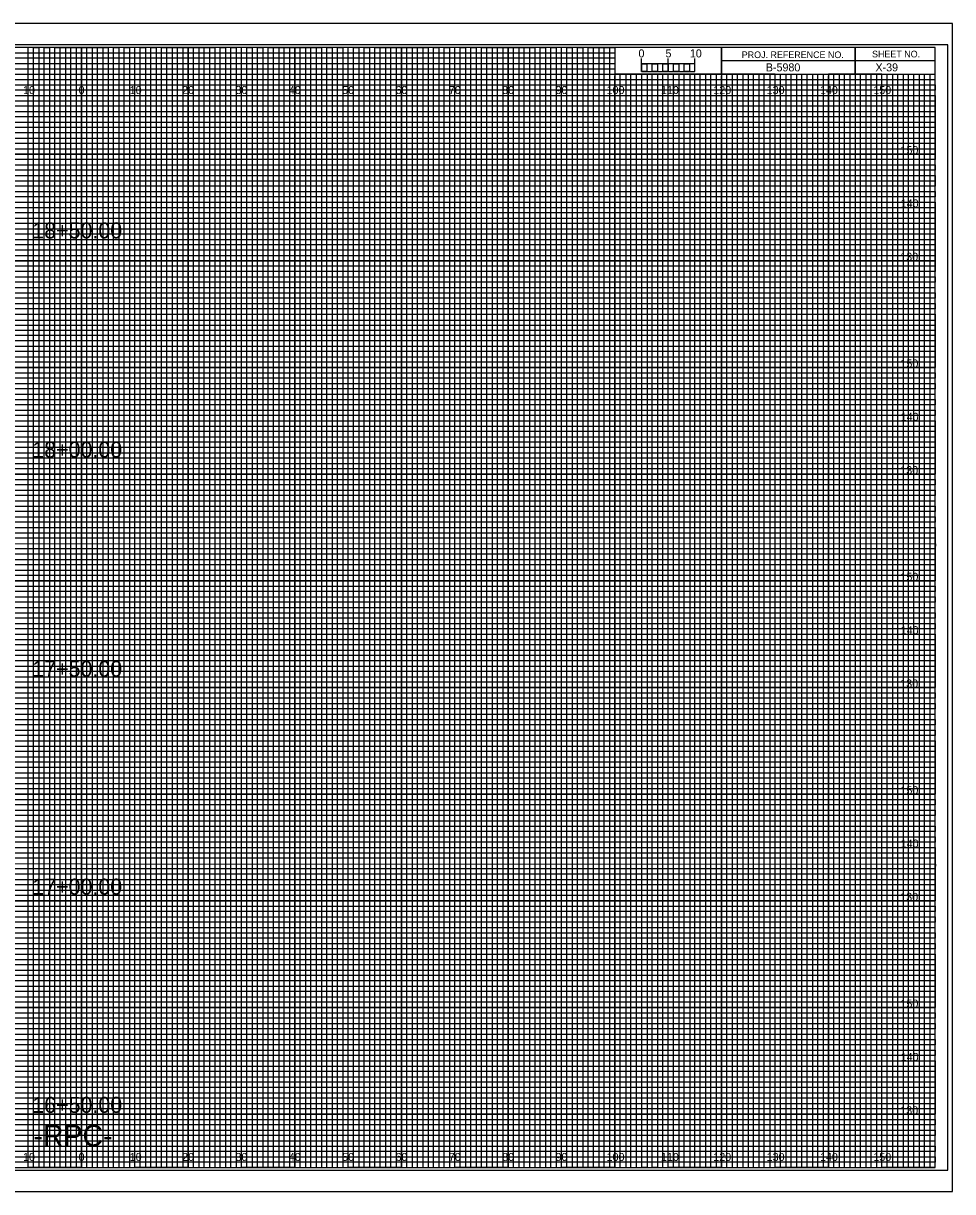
# Model space of a CAD drawing. Extents: x -13 to 323, y -5 to 874.
# Drawn here: x 149.1 to 323.3, y 215.5 to 434.5 of the extents above; entities that cross this region are included whole.
import ezdxf

# ---------------------------------------------------------------- set-up
doc = ezdxf.new("R2010")
doc.units = 0
for name, color, linetype in [('Exist Cross Section Cell', 7, 'Continuous'), ('Exist XS Center Line Elevation Label', 7, 'Continuous'), ('Exist XS Ground Line', 7, 'Continuous'), ('Prop CMT Conc Surface', 7, 'Continuous'), ('Prop CMT Concrete Structures', 7, 'Continuous'), ('Prop CMT Pvmt Course 1', 7, 'Continuous'), ('Prop CMT Pvmt Course 1 CG', 7, 'Continuous'), ('Prop CMT Pvmt Course 2', 7, 'Continuous'), ('Prop CMT Pvmt Course 3', 7, 'Continuous'), ('Prop CMT Pvmt Surface', 7, 'Continuous'), ('Prop CMT Pvmt Surface Shoulder', 7, 'Continuous'), ('Prop CMT Shld Paved Course 1', 7, 'Continuous'), ('Prop CMT Shld Paved Course 2', 7, 'Continuous'), ('Prop CMT Shld Paved Course 3', 7, 'Continuous'), ('Prop CMT Slope Grass', 7, 'Continuous'), ('Prop CMT Subgrade Earthwork', 7, 'Continuous'), ('Scratch_Level_1', 7, 'Continuous')]:
    doc.layers.add(name, color=color, linetype=linetype)

msp = doc.modelspace()

# ---------------------------------------------------------------- linework, layer by layer
at = {"layer": 'Exist XS Center Line Elevation Label'}
for points in [[(145, 220), (155, 220), (155, 430), (165, 430), (165, 220), (175, 220), (175, 430), (185, 430), (185, 220), (195, 220), (195, 430), (205, 430), (205, 220), (215, 220), (215, 430), (225, 430), (225, 220), (235, 220), (235, 430), (245, 430), (245, 220), (255, 220), (255, 430), (259.93, 430), (260, 430), (260, 425), (264.99, 425), (264.99, 220), (275, 220), (275, 425), (285, 425), (285, 220), (295, 220), (295, 425), (305, 425), (305, 220), (315, 220), (315, 425)], [(0, 425), (275, 425)], [(0, 405), (320, 405), (320, 415), (0, 415)], [(0, 385), (320, 385), (320, 395), (0, 395)], [(0, 365), (320, 365), (320, 375), (0, 375)], [(0, 345), (320, 345), (320, 355), (0, 355)], [(0, 325), (320, 325), (320, 335), (0, 335)], [(0, 305), (320, 305), (320, 315), (0, 315)], [(0, 285), (320, 285), (320, 295), (0, 295)], [(0, 265), (320, 265), (320, 275), (0, 275)], [(0, 245), (320, 245), (320, 255), (0, 255)], [(0, 225), (320, 225), (320, 235), (0, 235)]]:
    msp.add_lwpolyline(points, dxfattribs=at)
at = {"layer": 'Exist XS Ground Line'}
for p, q in [((150, 430), (140, 430)), ((150, 220), (150, 430)), ((170, 430), (160, 430)), ((160, 430), (160, 220)), ((170, 220), (170, 430)), ((190, 430), (180, 430)), ((180, 430), (180, 220)), ((190, 220), (190, 430)), ((210, 430), (200, 430)), ((200, 430), (200, 220)), ((210, 220), (210, 430)), ((230, 430), (220, 430)), ((220, 430), (220, 220)), ((230, 220), (230, 430)), ((250, 430), (240, 430)), ((240, 430), (240, 220)), ((250, 220), (250, 430)), ((260, 430), (260, 220)), ((270, 220), (270, 425)), ((290, 425), (280, 425)), ((280, 425), (280, 220)), ((290, 220), (290, 425)), ((310, 425), (300, 425)), ((300, 425), (300, 220)), ((310, 220), (310, 425)), ((160, 220), (150, 220)), ((180, 220), (170, 220)), ((200, 220), (190, 220)), ((220, 220), (210, 220)), ((240, 220), (230, 220)), ((260, 220), (250, 220)), ((280, 220), (270, 220)), ((300, 220), (290, 220)), ((320, 220), (310, 220)), ((320, 220), (320, 220))]:
    msp.add_line(p, q, dxfattribs=at)
for points in [[(0, 420), (320, 420), (320, 410), (0, 410)], [(0, 400), (320, 400), (320, 390), (0, 390)], [(0, 380), (320, 380), (320, 370), (0, 370)], [(0, 360), (320, 360), (320, 350), (0, 350)], [(0, 340), (320, 340), (320, 330), (0, 330)], [(0, 320), (320, 320), (320, 310), (0, 310)], [(0, 300), (320, 300), (320, 290), (0, 290)], [(0, 280), (320, 280), (320, 270), (0, 270)], [(0, 260), (320, 260), (320, 250), (0, 250)], [(0, 240), (320, 240), (320, 230), (0, 230)]]:
    msp.add_lwpolyline(points, dxfattribs=at)
at = {"layer": 'Prop CMT Pvmt Course 2'}
for p, q in [((265, 425.49), (265, 427.9)), ((265, 426.9), (265, 427.9)), ((270, 425.49), (270, 427.9)), ((275, 425.49), (275, 427.9)), ((275, 426.9), (275, 427.9))]:
    msp.add_line(p, q, dxfattribs=at)
for points in [[(275, 426.9), (265, 426.9), (265, 425.49), (275, 425.49)], [(265, 426.9), (266, 426.9), (266, 425.49), (265, 425.49)], [(267, 426.9), (268, 426.9), (268, 425.49), (267, 425.49)], [(269, 426.9), (270, 426.9), (270, 425.49), (269, 425.49)], [(271, 426.9), (272, 426.9), (272, 425.49), (271, 425.49)], [(273, 426.9), (274, 426.9), (274, 425.49), (273, 425.49)]]:
    msp.add_lwpolyline(points, close=True, dxfattribs=at)
at = {"layer": 'Prop CMT Pvmt Course 3'}
msp.add_lwpolyline([(-13.4, 215.5), (323.3, 215.5), (323.3, 434.5), (-13.4, 434.5)], close=True, dxfattribs=at)
at = {"layer": 'Prop CMT Pvmt Surface'}
for p, q in [((150, 220), (150, 430)), ((160, 220), (160, 430)), ((170, 220), (170, 430)), ((180, 220), (180, 430)), ((190, 220), (190, 430)), ((200, 220), (200, 430)), ((210, 220), (210, 430)), ((220, 220), (220, 430)), ((230, 220), (230, 430)), ((240, 220), (240, 430)), ((250, 220), (250, 430)), ((260, 220), (260, 424.69)), ((270, 220), (270, 424.69)), ((280, 220), (280, 424.69)), ((290, 220), (290, 424.69)), ((300, 220), (300, 424.69)), ((310, 220), (310, 424.69)), ((0, 420), (320, 420)), ((0, 410), (320, 410)), ((0, 400), (320, 400)), ((0, 390), (320, 390)), ((0, 380), (320, 380)), ((0, 370), (320, 370)), ((0, 360), (320, 360)), ((0, 350), (320, 350)), ((0, 340), (320, 340)), ((0, 330), (320, 330)), ((0, 320), (320, 320)), ((0, 310), (320, 310)), ((0, 300), (320, 300)), ((0, 290), (320, 290)), ((0, 280), (320, 280)), ((0, 270), (320, 270)), ((0, 260), (320, 260)), ((0, 250), (320, 250)), ((0, 240), (320, 240)), ((0, 230), (320, 230))]:
    msp.add_line(p, q, dxfattribs=at)
at = {"layer": 'Prop CMT Pvmt Surface Shoulder'}
for p, q in [((323.3, 434.5), (-13.4, 434.5)), ((-13.4, 215.5), (323.3, 215.5))]:
    msp.add_line(p, q, dxfattribs=at)
at = {"layer": 'Prop CMT Shld Paved Course 1'}
for p, q in [((0, 429), (260, 429)), ((260, 427.98), (0, 427.98)), ((260, 429), (260, 427.98)), ((0, 427), (260, 427)), ((260, 425.89), (0, 425.89)), ((260, 427), (260, 425.89)), ((0, 424), (320, 424))]:
    msp.add_line(p, q, dxfattribs=at)
for points in [[(0, 423), (270, 423), (320, 423), (320, 422), (0, 422)], [(0, 421), (320, 421), (320, 419), (0, 419)], [(0, 418), (320, 418), (320, 417), (0, 416.98)], [(0, 416), (320, 416), (320, 414), (0, 414)], [(0, 413), (320, 413), (320, 412), (0, 412)], [(0, 411), (320, 411), (320, 409), (0, 409)], [(0, 408), (320, 408), (320, 407), (0, 407)], [(0, 406), (320, 406), (320, 404), (0, 404)], [(0, 403), (320, 403), (320, 402), (0, 402)], [(0, 401), (320, 401), (320, 399), (0, 399)], [(0, 398), (320, 398), (320, 397), (0, 397)], [(0, 396), (320, 396), (320, 393.95), (320, 393), (320, 392), (0, 392)], [(0, 394), (320, 394), (320, 393), (0, 393)], [(0, 391), (320, 391), (320, 389), (0, 389.03)], [(0, 389.03), (320, 389), (320, 388), (0, 388)], [(0, 387), (320, 387), (320, 386), (0, 386)], [(0, 384), (320, 384), (320, 383), (0, 383)], [(0, 382), (320, 382), (320, 381), (0, 381)], [(-0.07, 378.89), (320, 378.89), (320, 377.88), (-0.07, 377.88)], [(0, 377), (320, 377), (320, 376), (0, 376)], [(0, 374), (320, 374), (320, 373), (0, 373)], [(0, 372), (320, 372), (320, 371), (0, 371)], [(0, 369), (320, 369), (320, 368), (0, 368)], [(0, 367), (320, 367), (320, 366), (0, 366)], [(0, 364), (320, 364), (320, 363), (0, 363)], [(0, 362), (320, 362), (320, 361), (0, 361)], [(0, 359), (320, 359), (319.99, 357.98), (0, 358)], [(0, 357), (320, 357), (320, 356), (0, 356)], [(0, 354), (320, 354), (320, 353), (0, 353)], [(0, 352), (320, 352), (320, 351), (0, 351)], [(0, 349), (320, 349), (320, 348), (0, 348)], [(0, 347), (320, 347), (320, 346), (0, 346)], [(0, 344), (320, 344), (320, 343), (0, 343)], [(0, 342), (320, 342), (320, 341), (0, 341)], [(0, 339), (320, 339), (320, 338), (0, 338)], [(0, 336.99), (320.07, 336.91), (320, 336), (0, 336)], [(0, 334), (320, 334), (320, 333), (0, 333)], [(0, 332), (320, 332), (320, 331), (0, 331)], [(0, 329), (320, 329), (320, 328), (0, 328)], [(0, 327), (320, 327), (320, 326), (0, 326)], [(0, 324), (320, 324), (320, 323), (0, 323)], [(0, 322), (320, 322), (320, 321), (0, 321)], [(0, 319), (320, 319), (320, 318), (0, 318)], [(0, 317), (320, 317), (320, 316), (0, 316)], [(0, 314), (320, 314), (320, 313), (0, 313)], [(0, 312), (320, 312), (320, 311), (0, 311)], [(0, 309), (320, 309), (320, 308), (0, 308)], [(0, 307), (320, 307), (320, 306), (0, 306)], [(0, 304), (320, 304), (320, 303), (0, 303)], [(0, 302), (320, 302), (320, 301), (0, 301)], [(0, 299), (320, 299), (319.99, 297.98), (0, 298)], [(0, 297), (320, 297), (320, 296), (0, 296)], [(0, 294), (320, 294), (320, 293), (0, 293)], [(0, 292), (320, 292), (320, 291), (0, 291)], [(0, 289), (320, 289), (320, 288), (0, 288)], [(0, 287), (320, 287), (320, 286), (0, 286)], [(0, 284), (320, 284), (320, 283), (0, 283)], [(0, 282), (320, 282), (320, 281), (0, 281)], [(0, 279), (320, 279), (320, 278), (0, 278)], [(0, 276.99), (320.07, 276.91), (320, 276), (0, 276)], [(0, 274), (320, 274), (320, 273), (0, 273)], [(0, 272), (320, 272), (320, 271), (0, 271)], [(0, 269), (320, 269), (320, 268), (0, 268)], [(0, 267), (320, 267), (320, 266), (0, 266)], [(0, 264), (320, 264), (320, 263), (0, 263)], [(0, 262), (320, 262), (320, 261), (0, 261)], [(0, 259), (320, 259), (320, 258), (0, 258)], [(0, 257), (320, 257), (320, 256), (0, 256)], [(0, 254), (320, 254), (320, 253), (0, 253)], [(0, 252), (320, 252), (320, 251), (0, 251)], [(0, 249), (320, 249), (320, 248), (0, 248)], [(0, 247), (320, 247), (320, 246), (0, 246)], [(0, 244), (320, 244), (320, 243), (0, 243)], [(0, 242), (320, 242), (320, 241), (0, 241)], [(0, 239), (320, 239), (320, 238), (0, 238)], [(0, 237), (320, 237), (320, 236), (0, 236)], [(0, 234), (320, 234), (320, 233), (0, 233)], [(0, 232), (320, 232), (320, 231), (0, 231)], [(0, 229), (320, 229), (320, 228), (0, 228)], [(0, 227), (320, 227), (320, 226), (0, 226)], [(0, 224), (320, 224), (320, 223), (0, 223)], [(0, 222), (320, 222), (320, 221), (0, 221)]]:
    msp.add_lwpolyline(points, dxfattribs=at)
at = {"layer": 'Prop CMT Shld Paved Course 2'}
for p, q in [((305, 430), (305, 425)), ((305, 425), (305, 430)), ((280, 427.5), (280, 425)), ((320, 427.49), (280, 427.49)), ((280, 425), (320, 425))]:
    msp.add_line(p, q, dxfattribs=at)
for points in [[(320, 430), (0, 430), (0, 220), (320, 220)], [(280, 430), (260, 430), (260, 425.03), (280, 425.03)], [(320, 430), (280, 430), (280, 425), (320, 425)]]:
    msp.add_lwpolyline(points, close=True, dxfattribs=at)
at = {"layer": 'Prop CMT Shld Paved Course 3'}
for p, q in [((267, 425), (266.01, 425)), ((266.01, 425), (266.01, 220)), ((267, 220), (267, 425)), ((269, 425), (268, 425)), ((268, 425), (268, 220)), ((269, 220), (269, 425)), ((266.01, 220), (265, 220)), ((268, 220), (267, 220))]:
    msp.add_line(p, q, dxfattribs=at)
for points in [[(150, 220), (151, 220), (151, 430), (152, 430), (152, 220)], [(152, 220), (153, 220), (153, 430), (154, 430), (154, 220)], [(155, 220), (156, 220), (156, 430), (157, 430), (157, 220)], [(157, 220), (158, 220), (158, 430), (159, 430), (159, 220)], [(160, 220), (161, 220), (161, 430), (162, 430), (162, 220)], [(162, 220), (163, 220), (163, 430), (164, 430), (164, 220)], [(165, 220), (166, 220), (166, 430), (167, 430), (167, 220)], [(167, 220), (168, 220), (168, 430), (169, 430), (169, 220)], [(170, 220), (171, 220), (171, 430), (172, 430), (172, 220)], [(172, 220), (173, 220), (173, 430), (174, 430), (174, 220)], [(175, 220), (176, 220), (176, 430), (177, 430), (177, 220)], [(177, 220), (178, 220), (178, 430), (179, 430), (179, 220)], [(180, 220), (181, 220), (181, 430), (182, 430), (182, 220)], [(182, 220), (183, 220), (183, 430), (184, 430), (184, 220)], [(185, 220), (186, 220), (186, 430), (187, 430), (187, 220)], [(187, 220), (188, 220), (188, 430), (189, 430), (189, 220)], [(190, 220), (191, 220), (191, 430), (192, 430), (192, 220)], [(192, 220), (193, 220), (193, 430), (194, 430), (194, 220)], [(195, 220), (196, 220), (196, 430), (197, 430), (197, 220)], [(197, 220), (198, 220), (198, 430), (199, 430), (199, 220)], [(200, 220), (201, 220), (201, 430), (202, 430), (202, 220)], [(202, 220), (203, 220), (203, 430), (204, 430), (204, 220)], [(205, 220), (206, 220), (206, 430), (207, 430), (207, 220)], [(207, 220), (208, 220), (208, 430), (209, 430), (209, 220)], [(210, 220), (211, 220), (211, 430), (212, 430), (212, 220)], [(212, 220), (213, 220), (213, 430), (214, 430), (214, 220)], [(215, 220), (216, 220), (216, 430), (217, 430), (217, 220)], [(217, 220), (218, 220), (218, 430), (219, 430), (219, 220)], [(220, 220), (221, 220), (221, 430), (222, 430), (222, 220)], [(222, 220), (223, 220), (223, 430), (224, 430), (224, 220)], [(225, 220), (226, 220), (226, 430), (227, 430), (227, 220)], [(227, 220), (228, 220), (228, 430), (229, 430), (229, 220)], [(230, 220), (231, 220), (231, 430), (232, 430), (232, 220)], [(232, 220), (233, 220), (233, 430), (234, 430), (234, 220)], [(235, 220), (236, 220), (236, 430), (237, 430), (237, 220)], [(237, 220), (238, 220), (238, 430), (239, 430), (239, 220)], [(240, 220), (241, 220), (241, 430), (242, 430), (242, 220)], [(242, 220), (243, 220), (243, 430), (244, 430), (244, 220)], [(245, 220), (246, 220), (246, 430), (247, 430), (247, 220)], [(247, 220), (248, 220), (248, 430), (249, 430), (249, 220)], [(250, 220), (251, 220), (251, 430), (252, 430), (252, 220)], [(252, 220), (253, 220), (253, 430), (254, 430), (254, 220)], [(255, 220), (256, 220), (256, 430), (257, 430), (257, 220)], [(257, 220), (258, 220), (258, 430), (259, 430), (259, 220)], [(260, 220), (261, 220), (261, 425), (262.02, 425), (262.02, 220)], [(262, 220), (263, 220), (263, 425), (263.99, 425), (263.99, 220)], [(270, 220), (270.98, 220), (270.98, 425), (272, 425), (272, 220)], [(272, 220), (273, 220), (273, 425), (274.05, 425), (274.05, 220)], [(275, 220), (276, 220), (276, 425), (277, 425), (277, 220)], [(277, 220), (278, 220), (278, 425), (279, 425), (279, 220)], [(280, 220), (281, 220), (281, 425), (282, 425), (282, 220)], [(282, 220), (283, 220), (283, 425), (284, 425), (284, 220)], [(285, 220), (286, 220), (286, 425), (287, 425), (287, 220)], [(287, 220), (288, 220), (288, 425), (289, 425), (289, 220)], [(290, 220), (291, 220), (291, 425), (292, 425), (292, 220)], [(292, 220), (293, 220), (293, 425), (294, 425), (294, 220)], [(295, 220), (296, 220), (296, 425), (297, 425), (297, 220)], [(297, 220), (298, 220), (298, 425), (299, 425), (299, 220)], [(300, 220), (301, 220), (301, 425), (302, 425), (302, 220)], [(302, 220), (303, 220), (303, 425), (304, 425), (304, 220)], [(305, 220), (306, 220), (306, 425), (307, 425), (307, 220)], [(307, 220), (308, 220), (308, 425), (309, 425), (309, 220)], [(310, 220), (311, 220), (311, 425), (312, 425), (312, 220)], [(312, 220), (313, 220), (313, 425), (314, 425), (314, 220)], [(315, 220), (316, 220), (316, 425), (317, 425), (317, 220)], [(317, 220), (318, 220), (318, 425), (319, 425), (319, 220)]]:
    msp.add_lwpolyline(points, dxfattribs=at)
at = {"layer": 'Prop CMT Subgrade Earthwork'}
msp.add_lwpolyline([(-10.8, 219.5), (322.4, 219.5), (322.4, 430.5), (-10.8, 430.5)], close=True, dxfattribs=at)

# ---------------------------------------------------------------- texts
at = {"layer": 'Exist Cross Section Cell'}
for s, p in [('10', (149.04, 421.25)), ('0', (159.45, 421.25)), ('0', (159.45, 421.25)), ('10', (169.04, 421.25)), ('20', (178.86, 421.25)), ('30', (188.86, 421.25)), ('40', (198.86, 421.25)), ('50', (208.86, 421.25)), ('60', (218.86, 421.25)), ('70', (228.86, 421.25)), ('80', (238.86, 421.25)), ('90', (248.86, 421.25)), ('100', (258.44, 421.25)), ('110', (268.62, 421.25)), ('120', (278.44, 421.25)), ('130', (288.44, 421.25)), ('140', (298.44, 421.25)), ('150', (308.44, 421.25)), ('10', (149.04, 221.25)), ('0', (159.45, 221.25)), ('0', (159.45, 221.25)), ('10', (169.04, 221.25)), ('20', (178.86, 221.25)), ('30', (188.86, 221.25)), ('40', (198.86, 221.25)), ('50', (208.86, 221.25)), ('60', (218.86, 221.25)), ('70', (228.86, 221.25)), ('80', (238.86, 221.25)), ('90', (248.86, 221.25)), ('100', (258.44, 221.25)), ('110', (268.62, 221.25)), ('120', (278.44, 221.25)), ('130', (288.44, 221.25)), ('140', (298.44, 221.25)), ('150', (308.44, 221.25))]:
    msp.add_text(s, height=1.5, dxfattribs=at).set_placement(p)
at = {"layer": 'Prop CMT Conc Surface'}
for s, p in [('5', (269.47, 428.12)), ('10', (274.04, 428.12))]:
    msp.add_text(s, height=1.5, dxfattribs=at).set_placement(p)
at = {"layer": 'Prop CMT Concrete Structures'}
msp.add_text('B-5980', height=1.5, dxfattribs=at).set_placement((288.28, 425.5))
at = {"layer": 'Prop CMT Pvmt Course 1'}
for s, p in [('150', (313.52, 410)), ('140', (313.57, 400)), ('130', (313.49, 390)), ('150', (313.52, 370)), ('140', (313.57, 360)), ('130', (313.49, 350)), ('150', (313.52, 330)), ('140', (313.57, 320)), ('130', (313.49, 310)), ('150', (313.52, 290)), ('140', (313.57, 280)), ('130', (313.49, 270)), ('150', (313.52, 250)), ('140', (313.57, 240)), ('130', (313.49, 230))]:
    msp.add_text(s, height=1.5, dxfattribs=at).set_placement(p)
at = {"layer": 'Prop CMT Pvmt Course 1 CG'}
msp.add_text('-RPC-', height=4, dxfattribs=at).set_placement((150.97, 224))
at = {"layer": 'Prop CMT Pvmt Course 2'}
msp.add_text('0', height=1.5, dxfattribs=at).set_placement((264.41, 428.12))
at = {"layer": 'Prop CMT Shld Paved Course 2'}
for s, p in [('PROJ. REFERENCE NO.', (283.77, 427.99)), ('SHEET NO.', (308.19, 428.12))]:
    msp.add_text(s, height=1.25, dxfattribs=at).set_placement(p)
at = {"layer": 'Prop CMT Slope Grass'}
for s, p in [('18+50.00', (150.77, 394.19)), ('18+00.00', (150.77, 353.1)), ('17+50.00', (150.77, 312.02)), ('17+00.00', (150.77, 271.17)), ('16+50.00', (150.77, 230.27))]:
    msp.add_text(s, height=3, dxfattribs=at).set_placement(p)
at = {"layer": 'Scratch_Level_1'}
msp.add_text('X-39', height=1.5, dxfattribs=at).set_placement((308.83, 425.5))

doc.saveas('drawing.dxf')
